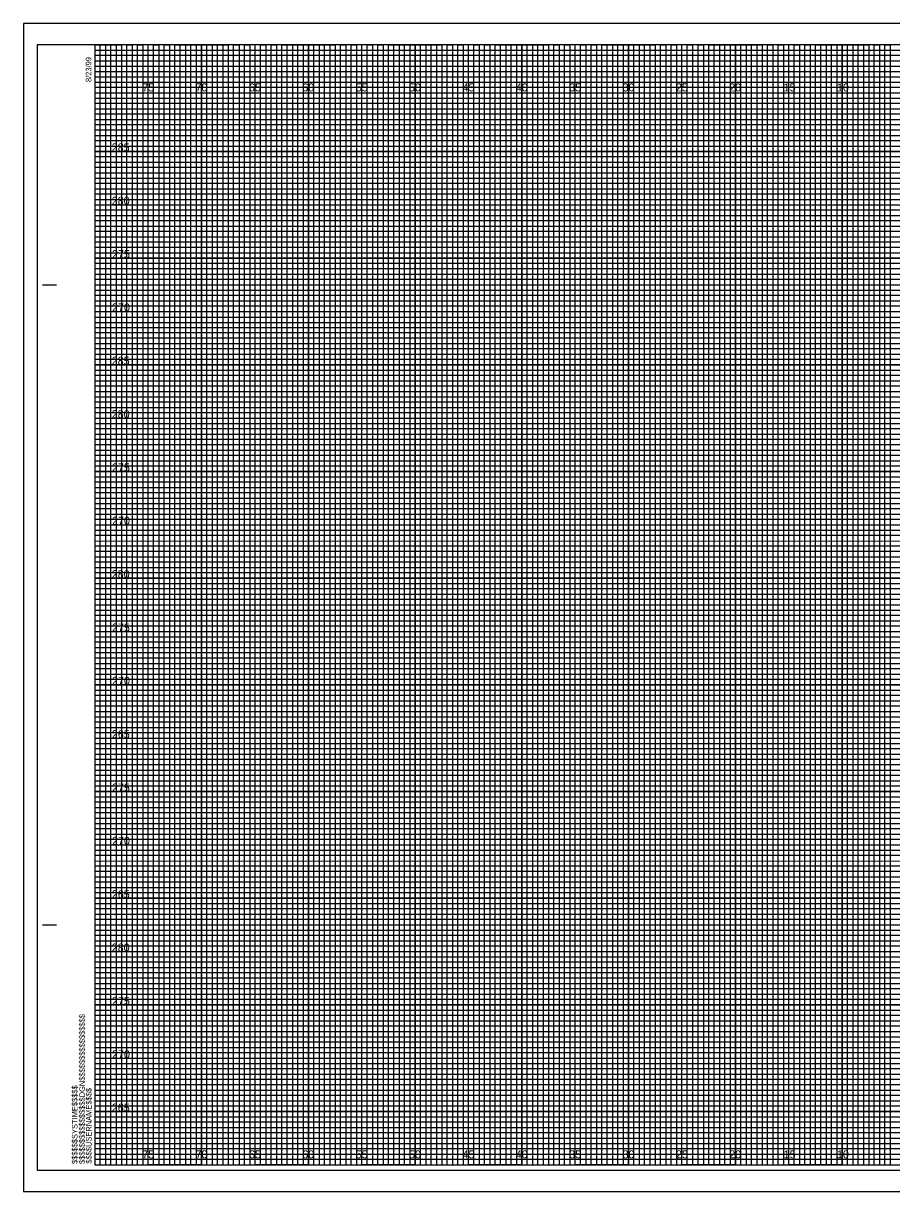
# Model space of a CAD drawing. Extents: x -7 to 162, y 658 to 767.
# Drawn here: x -6.7 to 74.6, y 657.5 to 767 of the extents above; entities that cross this region are included whole.
import ezdxf

# ---------------------------------------------------------------- set-up
doc = ezdxf.new("R2010")
doc.units = 0
for name, color, linetype in [('Prop XS Elevation Labels', 7, 'Continuous'), ('Prop XS Offset Labels', 7, 'Continuous'), ('Sheet Cross Section CELL', 7, 'Continuous'), ('Sheet Cross Section Grid Major CELL', 7, 'Continuous'), ('Sheet Cross Section Grid Middle CELL', 7, 'Continuous'), ('Sheet Cross Section Grid Minor 1 CELL', 7, 'Continuous'), ('Sheet Cross Section Grid Minor 2 CELL', 7, 'Continuous'), ('Sheet Cutting Line CELL', 7, 'Continuous'), ('Sheet DOT Grid CELL', 7, 'Continuous'), ('Sheet Plot Border Inside CELL', 7, 'Continuous'), ('Sheet Plot Border Outside CELL', 7, 'Continuous')]:
    doc.layers.add(name, color=color, linetype=linetype)

msp = doc.modelspace()

# ---------------------------------------------------------------- linework, layer by layer
at = {"layer": 'Sheet Cross Section CELL'}
for p, q in [((-4.9, 742.5), (-3.65, 742.5)), ((-4.85, 742.5), (-3.6, 742.5)), ((-4.9, 682.5), (-3.65, 682.5)), ((-4.85, 682.5), (-3.6, 682.5)), ((0, 660), (0, 660)), ((0, 660), (0, 660)), ((0, 660), (0, 660)), ((0, 660), (0, 660)), ((0, 660), (0, 660)), ((0, 660), (0, 660)), ((0, 660), (0, 660))]:
    msp.add_line(p, q, dxfattribs=at)
msp.add_lwpolyline([(160, 765), (0, 765), (0, 660), (160, 660)], close=True, dxfattribs=at)
at = {"layer": 'Sheet Cross Section Grid Major CELL'}
for p, q in [((5, 765), (0, 765)), ((5, 660), (5, 765)), ((15, 765), (10, 765)), ((10, 765), (10, 660)), ((15, 660), (15, 765)), ((25, 765), (20, 765)), ((20, 765), (20, 660)), ((25, 660), (25, 765)), ((35, 765), (30, 765)), ((30, 765), (30, 660)), ((35, 660), (35, 765)), ((45, 765), (40, 765)), ((40, 765), (40, 660)), ((45, 660), (45, 765)), ((55, 765), (50, 765)), ((50, 765), (50, 660)), ((55, 660), (55, 765)), ((65, 765), (60, 765)), ((60, 765), (60, 660)), ((65, 660), (65, 765)), ((75, 765), (70, 765)), ((70, 765), (70, 660)), ((10, 660), (5, 660)), ((20, 660), (15, 660)), ((30, 660), (25, 660)), ((40, 660), (35, 660)), ((50, 660), (45, 660)), ((60, 660), (55, 660)), ((70, 660), (65, 660))]:
    msp.add_line(p, q, dxfattribs=at)
for points in [[(0, 760), (160, 760), (160, 755), (0, 755)], [(0, 750), (160, 750), (160, 745), (0, 745)], [(0, 740), (160, 740), (160, 735), (0, 735)], [(0, 730), (160, 730), (160, 725), (0, 725)], [(0, 720), (160, 720), (160, 715), (0, 715)], [(0, 710), (160, 710), (160, 705), (0, 705)], [(0, 700), (160, 700), (160, 695), (0, 695)], [(0, 690), (160, 690), (160, 685), (0, 685)], [(0, 680), (160, 680), (160, 675), (0, 675)], [(0, 670), (160, 670), (160, 665), (0, 665)]]:
    msp.add_lwpolyline(points, dxfattribs=at)
at = {"layer": 'Sheet Cross Section Grid Middle CELL'}
for points in [[(0, 765), (2.5, 765), (2.5, 660), (7.5, 660), (7.5, 765), (12.5, 765), (12.5, 660), (17.5, 660), (17.5, 765), (22.5, 765), (22.5, 660), (27.5, 660), (27.5, 765), (32.5, 765), (32.5, 660), (37.5, 660), (37.5, 765), (42.5, 765), (42.5, 660), (47.5, 660), (47.5, 765), (52.5, 765), (52.5, 660), (57.5, 660), (57.5, 765), (62.5, 765), (62.5, 660), (67.5, 660), (67.5, 765), (72.5, 765), (72.5, 660), (77.5, 660)], [(0, 762.5), (137.5, 762.5)], [(0, 752.5), (160, 752.5), (160, 757.5), (0, 757.5)], [(0, 742.5), (160, 742.5), (160, 747.5), (0, 747.5)], [(0, 732.5), (160, 732.5), (160, 737.5), (0, 737.5)], [(0, 722.5), (160, 722.5), (160, 727.5), (0, 727.5)], [(0, 712.5), (160, 712.5), (160, 717.5), (0, 717.5)], [(0, 702.5), (160, 702.5), (160, 707.5), (0, 707.5)], [(0, 692.5), (160, 692.5), (160, 697.5), (0, 697.5)], [(0, 682.5), (160, 682.5), (160, 687.5), (0, 687.5)], [(0, 672.5), (160, 672.5), (160, 677.5), (0, 677.5)], [(0, 662.5), (160, 662.5), (160, 667.5), (0, 667.5)]]:
    msp.add_lwpolyline(points, dxfattribs=at)
at = {"layer": 'Sheet Cross Section Grid Minor 1 CELL'}
for p, q in [((0, 764.5), (130, 764.5)), ((130, 763.99), (0, 763.99)), ((0, 763.99), (0, 763.5)), ((0, 763.5), (130, 763.5)), ((130, 762.95), (0, 762.95)), ((0, 762.95), (0, 762)), ((0, 762), (160, 762))]:
    msp.add_line(p, q, dxfattribs=at)
for points in [[(0, 761.5), (135, 761.5), (160, 761.5), (160, 761), (0, 761)], [(0, 760.5), (160, 760.5), (160, 759.5), (0, 759.5)], [(0, 759), (160, 759), (160, 758.5), (0, 758.49)], [(0, 758), (160, 758), (160, 757), (0, 757)], [(0, 756.5), (160, 756.5), (160, 756), (0, 756)], [(0, 755.5), (160, 755.5), (160, 754.5), (0, 754.5)], [(0, 754), (160, 754), (160, 753.5), (0, 753.5)], [(0, 753), (160, 753), (160, 752), (0, 752)], [(0, 751.5), (160, 751.5), (160, 751), (0, 751)], [(0, 750.5), (160, 750.5), (160, 749.5), (0, 749.5)], [(0, 749), (160, 749), (160, 748.5), (0, 748.5)], [(0, 748), (160, 748), (160, 746.98), (160, 746.5), (160, 746), (0, 746)], [(0, 747), (160, 747), (160, 746.5), (0, 746.5)], [(0, 745.5), (160, 745.5), (160, 744.5), (0, 744.51)], [(0, 744.51), (160, 744.5), (160, 744), (0, 744)], [(0, 743.5), (160, 743.5), (160, 743), (0, 743)], [(0, 742), (160, 742), (160, 741.5), (0, 741.5)], [(0, 741), (160, 741), (160, 740.5), (0, 740.5)], [(-0.04, 739.45), (160, 739.45), (160, 738.94), (-0.04, 738.94)], [(0, 738.5), (160, 738.5), (160, 738), (0, 738)], [(0, 737), (160, 737), (160, 736.5), (0, 736.5)], [(0, 736), (160, 736), (160, 735.5), (0, 735.5)], [(0, 734.5), (160, 734.5), (160, 734), (0, 734)], [(0, 733.5), (160, 733.5), (160, 733), (0, 733)], [(0, 732), (160, 732), (160, 731.5), (0, 731.5)], [(0, 731), (160, 731), (160, 730.5), (0, 730.5)], [(0, 729.5), (160, 729.5), (160, 728.99), (0, 729)], [(0, 728.5), (160, 728.5), (160, 728), (0, 728)], [(0, 727), (160, 727), (160, 726.5), (0, 726.5)], [(0, 726), (160, 726), (160, 725.5), (0, 725.5)], [(0, 724.5), (160, 724.5), (160, 724), (0, 724)], [(0, 723.5), (160, 723.5), (160, 723), (0, 723)], [(0, 722), (160, 722), (160, 721.5), (0, 721.5)], [(0, 721), (160, 721), (160, 720.5), (0, 720.5)], [(0, 719.5), (160, 719.5), (160, 719), (0, 719)], [(0, 718.5), (160.03, 718.46), (160, 718), (0, 718)], [(0, 717), (160, 717), (160, 716.5), (0, 716.5)], [(0, 716), (160, 716), (160, 715.5), (0, 715.5)], [(0, 714.5), (160, 714.5), (160, 714), (0, 714)], [(0, 713.5), (160, 713.5), (160, 713), (0, 713)], [(0, 712), (160, 712), (160, 711.5), (0, 711.5)], [(0, 711), (160, 711), (160, 710.5), (0, 710.5)], [(0, 709.5), (160, 709.5), (160, 709), (0, 709)], [(0, 708.5), (160, 708.5), (160, 708), (0, 708)], [(0, 707), (160, 707), (160, 706.5), (0, 706.5)], [(0, 706), (160, 706), (160, 705.5), (0, 705.5)], [(0, 704.5), (160, 704.5), (160, 704), (0, 704)], [(0, 703.5), (160, 703.5), (160, 703), (0, 703)], [(0, 702), (160, 702), (160, 701.5), (0, 701.5)], [(0, 701), (160, 701), (160, 700.5), (0, 700.5)], [(0, 699.5), (160, 699.5), (160, 698.99), (0, 699)], [(0, 698.5), (160, 698.5), (160, 698), (0, 698)], [(0, 697), (160, 697), (160, 696.5), (0, 696.5)], [(0, 696), (160, 696), (160, 695.5), (0, 695.5)], [(0, 694.5), (160, 694.5), (160, 694), (0, 694)], [(0, 693.5), (160, 693.5), (160, 693), (0, 693)], [(0, 692), (160, 692), (160, 691.5), (0, 691.5)], [(0, 691), (160, 691), (160, 690.5), (0, 690.5)], [(0, 689.5), (160, 689.5), (160, 689), (0, 689)], [(0, 688.5), (160.03, 688.46), (160, 688), (0, 688)], [(0, 687), (160, 687), (160, 686.5), (0, 686.5)], [(0, 686), (160, 686), (160, 685.5), (0, 685.5)], [(0, 684.5), (160, 684.5), (160, 684), (0, 684)], [(0, 683.5), (160, 683.5), (160, 683), (0, 683)], [(0, 682), (160, 682), (160, 681.5), (0, 681.5)], [(0, 681), (160, 681), (160, 680.5), (0, 680.5)], [(0, 679.5), (160, 679.5), (160, 679), (0, 679)], [(0, 678.5), (160, 678.5), (160, 678), (0, 678)], [(0, 677), (160, 677), (160, 676.5), (0, 676.5)], [(0, 676), (160, 676), (160, 675.5), (0, 675.5)], [(0, 674.5), (160, 674.5), (160, 674), (0, 674)], [(0, 673.5), (160, 673.5), (160, 673), (0, 673)], [(0, 672), (160, 672), (160, 671.5), (0, 671.5)], [(0, 671), (160, 671), (160, 670.5), (0, 670.5)], [(0, 669.5), (160, 669.5), (160, 669), (0, 669)], [(0, 668.5), (160, 668.5), (160, 668), (0, 668)], [(0, 667), (160, 667), (160, 666.5), (0, 666.5)], [(0, 666), (160, 666), (160, 665.5), (0, 665.5)], [(0, 664.5), (160, 664.5), (160, 664), (0, 664)], [(0, 663.5), (160, 663.5), (160, 663), (0, 663)], [(0, 662), (160, 662), (160, 661.5), (0, 661.5)], [(0, 661), (160, 661), (160, 660.5), (0, 660.5)]]:
    msp.add_lwpolyline(points, dxfattribs=at)
at = {"layer": 'Sheet Cross Section Grid Minor 2 CELL'}
for points in [[(0, 660), (0.5, 660), (0.5, 765), (1, 765), (1, 660)], [(1, 660), (1.5, 660), (1.5, 765), (2, 765), (2, 660)], [(2.5, 660), (3, 660), (3, 765), (3.5, 765), (3.5, 660)], [(3.5, 660), (4, 660), (4, 765), (4.5, 765), (4.5, 660)], [(5, 660), (5.5, 660), (5.5, 765), (6, 765), (6, 660)], [(6, 660), (6.5, 660), (6.5, 765), (7, 765), (7, 660)], [(7.5, 660), (8, 660), (8, 765), (8.5, 765), (8.5, 660)], [(8.5, 660), (9, 660), (9, 765), (9.5, 765), (9.5, 660)], [(10, 660), (10.5, 660), (10.5, 765), (11, 765), (11, 660)], [(11, 660), (11.5, 660), (11.5, 765), (12, 765), (12, 660)], [(12.5, 660), (13, 660), (13, 765), (13.5, 765), (13.5, 660)], [(13.5, 660), (14, 660), (14, 765), (14.5, 765), (14.5, 660)], [(15, 660), (15.5, 660), (15.5, 765), (16, 765), (16, 660)], [(16, 660), (16.5, 660), (16.5, 765), (17, 765), (17, 660)], [(17.5, 660), (18, 660), (18, 765), (18.5, 765), (18.5, 660)], [(18.5, 660), (19, 660), (19, 765), (19.5, 765), (19.5, 660)], [(20, 660), (20.5, 660), (20.5, 765), (21, 765), (21, 660)], [(21, 660), (21.5, 660), (21.5, 765), (22, 765), (22, 660)], [(22.5, 660), (23, 660), (23, 765), (23.5, 765), (23.5, 660)], [(23.5, 660), (24, 660), (24, 765), (24.5, 765), (24.5, 660)], [(25, 660), (25.5, 660), (25.5, 765), (26, 765), (26, 660)], [(26, 660), (26.5, 660), (26.5, 765), (27, 765), (27, 660)], [(27.5, 660), (28, 660), (28, 765), (28.5, 765), (28.5, 660)], [(28.5, 660), (29, 660), (29, 765), (29.5, 765), (29.5, 660)], [(30, 660), (30.5, 660), (30.5, 765), (31, 765), (31, 660)], [(31, 660), (31.5, 660), (31.5, 765), (32, 765), (32, 660)], [(32.5, 660), (33, 660), (33, 765), (33.5, 765), (33.5, 660)], [(33.5, 660), (34, 660), (34, 765), (34.5, 765), (34.5, 660)], [(35, 660), (35.5, 660), (35.5, 765), (36, 765), (36, 660)], [(36, 660), (36.5, 660), (36.5, 765), (37, 765), (37, 660)], [(37.5, 660), (38, 660), (38, 765), (38.5, 765), (38.5, 660)], [(38.5, 660), (39, 660), (39, 765), (39.5, 765), (39.5, 660)], [(40, 660), (40.5, 660), (40.5, 765), (41, 765), (41, 660)], [(41, 660), (41.5, 660), (41.5, 765), (42, 765), (42, 660)], [(42.5, 660), (43, 660), (43, 765), (43.5, 765), (43.5, 660)], [(43.5, 660), (44, 660), (44, 765), (44.5, 765), (44.5, 660)], [(45, 660), (45.5, 660), (45.5, 765), (46, 765), (46, 660)], [(46, 660), (46.5, 660), (46.5, 765), (47, 765), (47, 660)], [(47.5, 660), (48, 660), (48, 765), (48.5, 765), (48.5, 660)], [(48.5, 660), (49, 660), (49, 765), (49.5, 765), (49.5, 660)], [(50, 660), (50.5, 660), (50.5, 765), (51, 765), (51, 660)], [(51, 660), (51.5, 660), (51.5, 765), (52, 765), (52, 660)], [(52.5, 660), (53, 660), (53, 765), (53.5, 765), (53.5, 660)], [(53.5, 660), (54, 660), (54, 765), (54.5, 765), (54.5, 660)], [(55, 660), (55.5, 660), (55.5, 765), (56, 765), (56, 660)], [(56, 660), (56.5, 660), (56.5, 765), (57, 765), (57, 660)], [(57.5, 660), (58, 660), (58, 765), (58.5, 765), (58.5, 660)], [(58.5, 660), (59, 660), (59, 765), (59.5, 765), (59.5, 660)], [(60, 660), (60.5, 660), (60.5, 765), (61, 765), (61, 660)], [(61, 660), (61.5, 660), (61.5, 765), (62, 765), (62, 660)], [(62.5, 660), (63, 660), (63, 765), (63.5, 765), (63.5, 660)], [(63.5, 660), (64, 660), (64, 765), (64.5, 765), (64.5, 660)], [(65, 660), (65.5, 660), (65.5, 765), (66, 765), (66, 660)], [(66, 660), (66.5, 660), (66.5, 765), (67, 765), (67, 660)], [(67.5, 660), (68, 660), (68, 765), (68.5, 765), (68.5, 660)], [(68.5, 660), (69, 660), (69, 765), (69.5, 765), (69.5, 660)], [(70, 660), (70.5, 660), (70.5, 765), (71, 765), (71, 660)], [(71, 660), (71.5, 660), (71.5, 765), (72, 765), (72, 660)], [(72.5, 660), (73, 660), (73, 765), (73.5, 765), (73.5, 660)], [(73.5, 660), (74, 660), (74, 765), (74.5, 765), (74.5, 660)]]:
    msp.add_lwpolyline(points, dxfattribs=at)
at = {"layer": 'Sheet Cutting Line CELL'}
for p, q in [((161.65, 767), (-6.7, 767)), ((-6.7, 767), (-6.7, 657.5)), ((-6.7, 657.5), (161.65, 657.5))]:
    msp.add_line(p, q, dxfattribs=at)
at = {"layer": 'Sheet DOT Grid CELL'}
for p, q in [((5, 660), (5, 765)), ((10, 660), (10, 765)), ((15, 660), (15, 765)), ((20, 660), (20, 765)), ((25, 660), (25, 765)), ((30, 660), (30, 765)), ((35, 660), (35, 765)), ((40, 660), (40, 765)), ((45, 660), (45, 765)), ((50, 660), (50, 765)), ((55, 660), (55, 765)), ((60, 660), (60, 765)), ((65, 660), (65, 765)), ((70, 660), (70, 765)), ((0, 760), (160, 760)), ((0, 755), (160, 755)), ((0, 750), (160, 750)), ((0, 745), (160, 745)), ((0, 740), (160, 740)), ((0, 735), (160, 735)), ((0, 730), (160, 730)), ((0, 725), (160, 725)), ((0, 720), (160, 720)), ((0, 715), (160, 715)), ((0, 710), (160, 710)), ((0, 705), (160, 705)), ((0, 700), (160, 700)), ((0, 695), (160, 695)), ((0, 690), (160, 690)), ((0, 685), (160, 685)), ((0, 680), (160, 680)), ((0, 675), (160, 675)), ((0, 670), (160, 670)), ((0, 665), (160, 665))]:
    msp.add_line(p, q, dxfattribs=at)
at = {"layer": 'Sheet Plot Border Inside CELL'}
msp.add_lwpolyline([(-5.4, 659.5), (161.2, 659.5), (161.2, 765), (-5.4, 765)], close=True, dxfattribs=at)
at = {"layer": 'Sheet Plot Border Outside CELL'}
msp.add_lwpolyline([(-6.7, 657.5), (161.65, 657.5), (161.65, 767), (-6.7, 767)], close=True, dxfattribs=at)

# ---------------------------------------------------------------- texts
at = {"layer": 'Prop XS Elevation Labels'}
for s, p in [('285', (1.58, 755)), ('280', (1.58, 750)), ('275', (1.61, 745)), ('270', (1.61, 740)), ('285', (1.58, 735)), ('280', (1.58, 730)), ('275', (1.61, 725)), ('270', (1.61, 720)), ('280', (1.58, 715)), ('275', (1.61, 710)), ('270', (1.61, 705)), ('265', (1.59, 700)), ('275', (1.61, 695)), ('270', (1.61, 690)), ('265', (1.59, 685)), ('280', (1.58, 680)), ('275', (1.61, 675)), ('270', (1.61, 670)), ('265', (1.59, 665))]:
    msp.add_text(s, height=0.75, dxfattribs=at).set_placement(p)
at = {"layer": 'Prop XS Offset Labels'}
for s, p in [('75', (4.44, 760.62)), ('70', (9.43, 760.62)), ('65', (14.44, 760.62)), ('60', (19.43, 760.62)), ('55', (24.44, 760.62)), ('50', (29.43, 760.62)), ('45', (34.44, 760.62)), ('40', (39.43, 760.62)), ('35', (44.44, 760.62)), ('30', (49.43, 760.62)), ('25', (54.44, 760.62)), ('20', (59.43, 760.62)), ('15', (64.53, 760.62)), ('10', (69.52, 760.62)), ('70', (9.43, 660.62)), ('65', (14.44, 660.62)), ('60', (19.43, 660.62)), ('50', (29.43, 660.62)), ('40', (39.43, 660.62)), ('35', (44.44, 660.62)), ('30', (49.43, 660.62)), ('25', (54.44, 660.62)), ('20', (59.43, 660.62)), ('10', (69.52, 660.62)), ('75', (4.44, 660.62)), ('55', (24.44, 660.62)), ('45', (34.44, 660.62)), ('15', (64.53, 660.62))]:
    msp.add_text(s, height=0.75, dxfattribs=at).set_placement(p)
at = {"layer": 'Sheet Cross Section CELL'}
for s, p in [('8/23/99', (-0.33, 761.5)), ('$$$$$$$$$$$$$$$$DGN$$$$$$$$$$$$$$$$', (-0.94, 660.09)), ('$$$$$$SYSTIME$$$$$', (-1.63, 660.09)), ('$$$$USERNAME$$$$', (-0.31, 660.12))]:
    msp.add_text(s, height=0.525, rotation=90, dxfattribs=at).set_placement(p)

doc.saveas('drawing.dxf')
